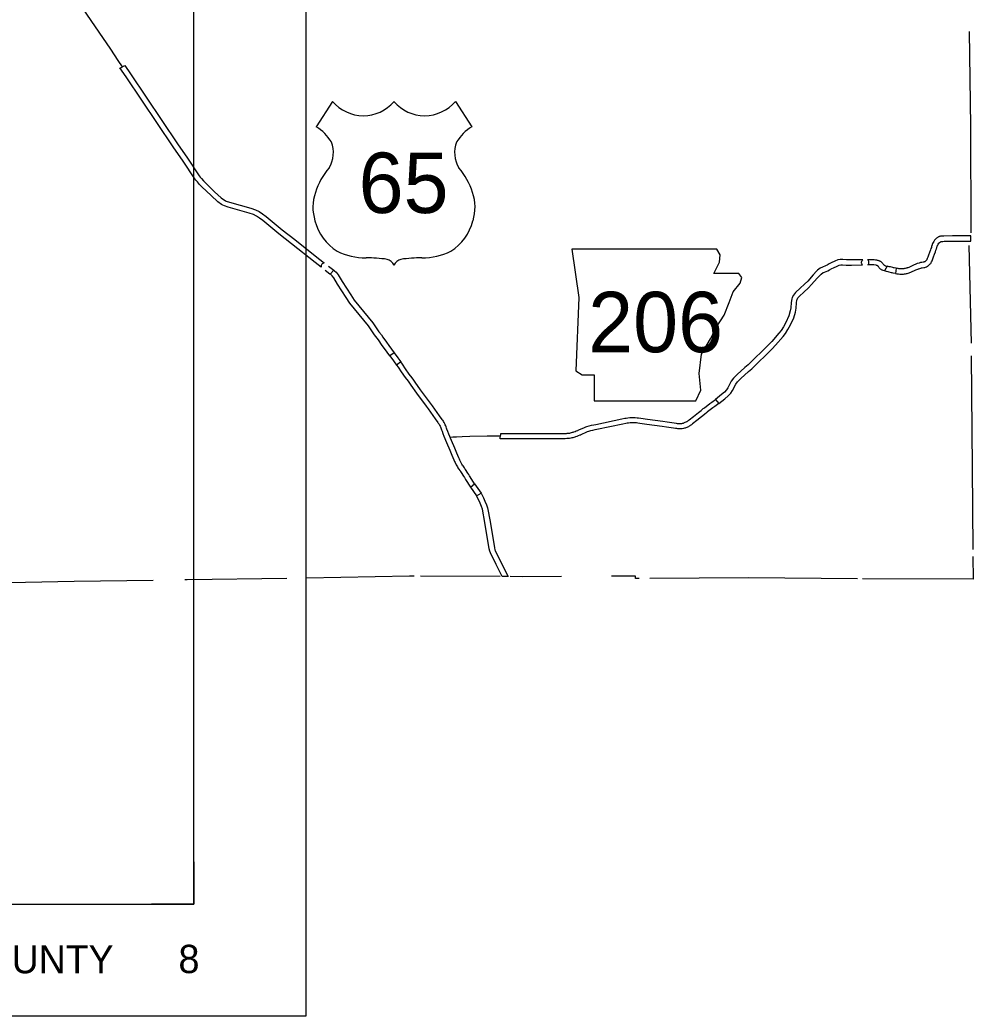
# Model space of a CAD drawing. Extents: x 77230 to 630905, y 790554 to 1662844.
# Drawn here: x 578093 to 623064, y 1483324 to 1530346 of the extents above; entities that cross this region are included whole.
import ezdxf

# ---------------------------------------------------------------- set-up
doc = ezdxf.new("R2010")
doc.units = 0
for name, color, linetype in [('Level 10', 7, 'Continuous'), ('Level 15', 7, 'Continuous'), ('Level 24', 7, 'Continuous'), ('Level 25', 7, 'Continuous'), ('Level 28', 7, 'Continuous'), ('Level 43', 7, 'Continuous')]:
    doc.layers.add(name, color=color, linetype=linetype)

msp = doc.modelspace()

# ---------------------------------------------------------------- linework, layer by layer
at = {"layer": 'Level 10'}
for points in [[(619605, 1518350), (619655, 1518346), (619690, 1518346), (619740, 1518348), (619780, 1518349), (619831, 1518354), (619876, 1518362), (619920, 1518370), (619961, 1518380), (620001, 1518389), (620042, 1518402), (620085, 1518418), (620130, 1518438), (620359, 1518544), (620459, 1518586), (620483, 1518596), (620500, 1518603), (620595, 1518630), (620633, 1518644), (620641, 1518646), (620644, 1518647), (620670, 1518650), (620742, 1518656), (620785, 1518665), (620822, 1518678), (620864, 1518695), (620907, 1518716), (620952, 1518745), (620984, 1518770), (621016, 1518798), (621042, 1518826), (621065, 1518852), (621081, 1518878), (621094, 1518900), (621107, 1518923), (621131, 1518977), (621149, 1519018), (621166, 1519067), (621198, 1519162), (621245, 1519290), (621285, 1519405), (621308, 1519470), (621327, 1519511), (621340, 1519543), (621346, 1519562), (621352, 1519582), (621369, 1519663), (621371, 1519670), (621377, 1519681), (621398, 1519718), (621422, 1519757), (621452, 1519803), (621458, 1519811), (621467, 1519821), (621480, 1519833), (621495, 1519847), (621508, 1519856), (621523, 1519866), (621540, 1519877), (621543, 1519878), (621544, 1519879), (621550, 1519881), (621559, 1519884), (621563, 1519886), (621570, 1519887), (621597, 1519891), (621633, 1519894), (621694, 1519895), (622100, 1519899), (622957, 1519897)], [(622957, 1519897), (622958, 1520147), (622099, 1520149), (621690, 1520145), (621620, 1520144), (621572, 1520139), (621526, 1520134), (621497, 1520127), (621480, 1520122), (621464, 1520116), (621447, 1520110), (621427, 1520100), (621411, 1520091), (621389, 1520077), (621364, 1520061), (621336, 1520040), (621310, 1520017), (621286, 1519993), (621264, 1519969), (621249, 1519948), (621211, 1519891), (621184, 1519847), (621154, 1519796), (621137, 1519759), (621127, 1519727), (621110, 1519645), (621107, 1519637), (621105, 1519629), (621097, 1519611), (621076, 1519563), (621049, 1519488), (621009, 1519374), (620962, 1519245), (620930, 1519149), (620916, 1519109), (620902, 1519078), (620882, 1519033), (620877, 1519023), (620869, 1519011), (620863, 1519002), (620855, 1518993), (620841, 1518977), (620825, 1518963), (620807, 1518949), (620783, 1518933), (620762, 1518923), (620735, 1518912), (620718, 1518906), (620706, 1518904), (620647, 1518899), (620608, 1518895), (620579, 1518889), (620551, 1518880), (620517, 1518867), (620424, 1518841), (620392, 1518830), (620361, 1518816), (620258, 1518772), (620027, 1518666), (619989, 1518649), (619959, 1518638), (619936, 1518630), (619906, 1518623), (619868, 1518615), (619831, 1518608), (619799, 1518602), (619763, 1518599), (619731, 1518597), (619687, 1518596), (619665, 1518596), (619622, 1518600)], [(617860, 1519028), (617323, 1519023), (617091, 1519027), (616914, 1519038), (616797, 1519034), (616682, 1519014), (616546, 1518959), (616372, 1518876), (616272, 1518825), (616180, 1518770), (616107, 1518736), (615958, 1518677), (615857, 1518630), (615730, 1518531), (615675, 1518481), (615525, 1518321), (615261, 1518020), (615117, 1517871), (614906, 1517677), (614687, 1517486), (614586, 1517356), (614533, 1517244)], [(617853, 1518778), (617840, 1518793), (617818, 1518830), (617807, 1518864), (617804, 1518914), (617816, 1518964), (617829, 1518990), (617860, 1519028)], [(618096, 1519030), (618394, 1519032)], [(618106, 1518780), (618126, 1518805), (618141, 1518834), (618153, 1518881), (618147, 1518947), (618120, 1519002), (618096, 1519030)], [(618394, 1519032), (618464, 1519023), (618513, 1519015), (618545, 1519009), (618576, 1519002), (618598, 1518995), (618619, 1518987), (618638, 1518979), (618663, 1518968), (618686, 1518955), (618712, 1518939), (618742, 1518915), (618764, 1518895), (618782, 1518875), (618802, 1518850), (618821, 1518823), (618835, 1518806), (618850, 1518788), (618857, 1518781), (618862, 1518776), (618867, 1518772), (618872, 1518769), (618885, 1518762), (618902, 1518754), (618921, 1518746), (618943, 1518738), (619004, 1518719), (618883, 1518500)], [(614766, 1517151), (614800, 1517224), (614869, 1517314), (615073, 1517490), (615292, 1517692), (615445, 1517850), (615710, 1518153), (615850, 1518302), (615891, 1518339), (615988, 1518416), (616057, 1518447), (616207, 1518506), (616297, 1518549), (616393, 1518606), (616482, 1518651), (616647, 1518730), (616751, 1518773), (616823, 1518785), (616910, 1518788), (617081, 1518777), (617322, 1518773), (617853, 1518778)], [(618389, 1518782), (618106, 1518780)], [(618883, 1518500), (618829, 1518514), (618799, 1518526), (618772, 1518539), (618745, 1518554), (618724, 1518567), (618702, 1518584), (618684, 1518600), (618667, 1518618), (618641, 1518647), (618620, 1518674), (618601, 1518701), (618592, 1518713), (618586, 1518719), (618580, 1518724), (618568, 1518733), (618556, 1518741), (618549, 1518746), (618539, 1518750), (618529, 1518754), (618520, 1518757), (618510, 1518760), (618492, 1518765), (618470, 1518769), (618389, 1518782)], [(619408, 1518373), (619291, 1518399), (619255, 1518407), (619220, 1518415), (619111, 1518441), (619060, 1518451), (618977, 1518468), (618933, 1518479), (618883, 1518500)], [(619437, 1518621), (619347, 1518643), (619309, 1518651), (619277, 1518658), (619163, 1518686), (619108, 1518696), (619004, 1518719)], [(619622, 1518600), (619569, 1518603), (619531, 1518607), (619503, 1518609), (619437, 1518621), (619408, 1518373)], [(619408, 1518373), (619472, 1518361), (619509, 1518358), (619549, 1518354), (619605, 1518350)], [(614533, 1517244), (614513, 1517183), (614485, 1517015), (614466, 1516763), (614440, 1516610), (614368, 1516379), (614229, 1516066), (614117, 1515861), (614006, 1515691), (613907, 1515561), (613563, 1515162), (613414, 1515003), (612457, 1514065), (612297, 1513932), (611934, 1513604), (611766, 1513431), (611655, 1513287), (611491, 1512982), (611428, 1512885), (611335, 1512779), (611194, 1512658), (610908, 1512433), (611063, 1512237)], [(611063, 1512237), (611353, 1512465), (611511, 1512601), (611628, 1512734), (611706, 1512855), (611865, 1513151), (611955, 1513266), (612108, 1513424), (612461, 1513743), (612625, 1513879), (613592, 1514828), (613748, 1514995), (614101, 1515404), (614210, 1515547), (614331, 1515732), (614454, 1515955), (614602, 1516291), (614683, 1516552), (614714, 1516733), (614733, 1516985), (614756, 1517123), (614766, 1517151)], [(604835, 1511156), (604950, 1511185), (605058, 1511210), (605169, 1511234), (605269, 1511253), (606492, 1511510), (606632, 1511543), (606703, 1511555), (606772, 1511566), (606865, 1511577), (606960, 1511581), (607048, 1511581), (607118, 1511577), (607209, 1511568), (607285, 1511558), (607382, 1511546), (607709, 1511498), (608429, 1511399), (608627, 1511370), (608969, 1511323), (609052, 1511310), (609105, 1511303), (609146, 1511300), (609180, 1511298), (609220, 1511297), (609265, 1511297), (609316, 1511300), (609354, 1511305), (609380, 1511310), (609397, 1511316), (609419, 1511325), (609451, 1511338), (609484, 1511354), (609520, 1511370), (609554, 1511388), (609572, 1511398), (609589, 1511409), (609612, 1511423), (609634, 1511439), (609675, 1511471), (609869, 1511625), (610103, 1511816), (610240, 1511913), (610333, 1511998), (610386, 1512041), (610641, 1512234), (610738, 1512307), (610908, 1512433), (611063, 1512237)], [(611063, 1512237), (610887, 1512106), (610791, 1512035), (610540, 1511844), (610495, 1511808), (610397, 1511718), (610255, 1511617), (610026, 1511430), (609829, 1511274), (609784, 1511239), (609750, 1511214), (609720, 1511196), (609702, 1511185), (609677, 1511170), (609630, 1511145), (609588, 1511126), (609553, 1511110), (609514, 1511093), (609483, 1511081), (609445, 1511068), (609395, 1511058), (609338, 1511051), (609273, 1511047), (609215, 1511047), (609168, 1511049), (609129, 1511051), (609080, 1511055), (609017, 1511063), (608933, 1511076), (608592, 1511123), (608394, 1511152), (607673, 1511250), (607348, 1511298), (607253, 1511310), (607180, 1511320), (607098, 1511328), (607040, 1511331), (606966, 1511331), (606885, 1511328), (606805, 1511318), (606745, 1511309), (606683, 1511298), (606546, 1511266), (605317, 1511007), (605219, 1510989), (605113, 1510966), (605009, 1510942), (604914, 1510918)], [(604914, 1510918), (604863, 1510896), (604827, 1510879), (604559, 1510761), (604535, 1510750), (604510, 1510740), (604431, 1510709), (604371, 1510686), (604313, 1510667), (604271, 1510653), (604226, 1510639), (604181, 1510627), (604137, 1510614), (604081, 1510600), (604029, 1510592), (603982, 1510587), (603936, 1510583), (603891, 1510581), (603811, 1510577), (603408, 1510577), (602990, 1510577), (602545, 1510577), (601722, 1510577), (601409, 1510577), (600745, 1510574)], [(600788, 1510824), (601408, 1510827), (601722, 1510827), (602545, 1510827), (602990, 1510827), (603408, 1510827), (603806, 1510827), (603878, 1510830), (603919, 1510833), (603957, 1510836), (603996, 1510840), (604032, 1510846), (604072, 1510855), (604112, 1510867), (604157, 1510880), (604196, 1510891), (604234, 1510904), (604287, 1510921), (604340, 1510942), (604415, 1510971), (604435, 1510980), (604458, 1510990), (604724, 1511107), (604761, 1511124), (604800, 1511141), (604835, 1511156)], [(599318, 1510681), (598964, 1510671), (598691, 1510658), (598519, 1510647), (598395, 1510639)], [(600772, 1510699), (600141, 1510696), (599317, 1510681)]]:
    msp.add_lwpolyline(points, dxfattribs=at)
msp.add_arc((599357, 1510942), 1435, 345.1612, 355.3083, dxfattribs=at)
at = {"layer": 'Level 15'}
for points in [[(580426, 1531556), (580484, 1531517), (580674, 1531354), (580755, 1531280), (580835, 1531194), (580892, 1531123), (582361, 1528958), (582710, 1528428)], [(582710, 1528428), (582923, 1528130)], [(590301, 1520252), (589549, 1520871), (589392, 1520992), (589254, 1521085), (589106, 1521154), (588912, 1521223), (587912, 1521507), (587740, 1521564), (587662, 1521599), (587610, 1521629), (587429, 1521761), (587108, 1522055), (586668, 1522473), (586568, 1522579), (586464, 1522697), (586397, 1522780), (586345, 1522852), (585799, 1523680), (585328, 1524363), (583105, 1527660), (582806, 1528078)], [(583036, 1528187), (583310, 1527802), (585535, 1524503), (586006, 1523819), (586552, 1522993), (586596, 1522931), (586655, 1522858), (586753, 1522747), (586845, 1522650), (587279, 1522237), (587588, 1521955), (587748, 1521838), (587777, 1521821), (587831, 1521797), (587986, 1521746), (588988, 1521461), (589201, 1521386), (589378, 1521303), (589538, 1521195), (589705, 1521067), (590460, 1520445)], [(592299, 1518680), (592023, 1518894), (590902, 1519783), (590301, 1520252)], [(590460, 1520445), (591056, 1519980), (592178, 1519091), (592452, 1518877)], [(592496, 1518530), (592719, 1518363), (592738, 1518347)], [(592646, 1518730), (592906, 1518535)], [(592738, 1518347), (592905, 1518534), (592935, 1518508), (593008, 1518438), (593115, 1518308), (593289, 1518002), (593699, 1517375), (593858, 1517122), (594738, 1516053), (595031, 1515626), (595149, 1515480), (595223, 1515378), (595382, 1515128), (595495, 1514985), (595754, 1514630)], [(595754, 1514630), (595548, 1514489), (595296, 1514833), (595178, 1514983), (595016, 1515238), (594950, 1515328), (594830, 1515476), (594538, 1515903), (593655, 1516975), (593488, 1517240), (593075, 1517872), (592909, 1518166), (592824, 1518268), (592769, 1518322), (592738, 1518347)], [(595754, 1514630), (595927, 1514393), (596064, 1514199)], [(595548, 1514489), (595724, 1514248), (595859, 1514057)], [(597890, 1511657), (597563, 1512129), (597458, 1512262), (597000, 1512881), (596748, 1513240), (596685, 1513339), (596605, 1513448), (596462, 1513622), (596280, 1513873), (596142, 1514089), (596064, 1514199), (595859, 1514057)], [(595859, 1514057), (595935, 1513949), (596074, 1513732), (596264, 1513469), (596408, 1513295), (596478, 1513199), (596540, 1513101), (596797, 1512735), (597260, 1512110), (597362, 1511981), (597684, 1511515)], [(597684, 1511515), (597813, 1511344), (597830, 1511318), (597847, 1511294), (597868, 1511260), (597889, 1511222), (597915, 1511171), (597932, 1511134), (597949, 1511090), (597968, 1511045), (597988, 1510995), (598008, 1510939), (598052, 1510825), (598100, 1510702), (598225, 1510392), (598376, 1510032), (598473, 1509797), (598565, 1509580), (598583, 1509539), (598599, 1509504), (598625, 1509450), (598680, 1509346), (598731, 1509253), (598759, 1509205), (598791, 1509152), (598859, 1509057), (598881, 1509023), (598907, 1508984), (599015, 1508814), (599062, 1508746), (599099, 1508688), (599120, 1508653), (599350, 1508294), (599546, 1508448)], [(599546, 1508448), (599333, 1508784), (599312, 1508820), (599270, 1508885), (599223, 1508952), (599117, 1509119), (599090, 1509160), (599065, 1509199), (598999, 1509290), (598974, 1509332), (598949, 1509376), (598900, 1509465), (598848, 1509562), (598826, 1509610), (598811, 1509642), (598795, 1509679), (598703, 1509893), (598607, 1510128), (598456, 1510488), (598332, 1510794), (598286, 1510915), (598242, 1511027), (598222, 1511083), (598200, 1511139), (598181, 1511186), (598162, 1511232), (598140, 1511279), (598110, 1511340), (598083, 1511387), (598056, 1511430), (598036, 1511460), (598015, 1511490), (597890, 1511657)], [(599350, 1508294), (599629, 1507886)], [(599546, 1508448), (599849, 1508004)], [(599629, 1507886), (599849, 1508004), (599965, 1507788), (600033, 1507637), (600104, 1507458)], [(599869, 1507371), (599803, 1507540), (599741, 1507678), (599629, 1507886)], [(601128, 1504066), (600847, 1504068), (600558, 1504636), (600293, 1505198), (600268, 1505263), (600240, 1505382), (600028, 1506626), (599912, 1507249), (599869, 1507371)], [(600104, 1507458), (600154, 1507313), (600274, 1506670), (600485, 1505432), (600507, 1505337), (600523, 1505296), (600783, 1504746), (601128, 1504066)]]:
    msp.add_lwpolyline(points, dxfattribs=at)
for centre, radius, start, end in [((581559, 1531008), 3184, 293.0661, 297.6373), ((592473, 1518703), 175, 96.6048, 187.7743)]:
    msp.add_arc(centre, radius, start, end, dxfattribs=at)
at = {"layer": 'Level 24'}
msp.add_lwpolyline([(604128, 1519524), (604470, 1517240), (604318, 1513776), (604623, 1513586), (605194, 1513586), (605194, 1512368), (609990, 1512368), (610218, 1512863), (610142, 1513662), (610256, 1514576), (610675, 1515299), (610941, 1515832), (611322, 1516403), (611551, 1517012), (611741, 1517507), (612083, 1517925), (612160, 1518192), (612007, 1518382), (610827, 1518382), (611094, 1518915), (611132, 1519258), (610974, 1519521)], close=True, dxfattribs=at)
msp.add_lwpolyline([(604128, 1519524), (604470, 1517240), (604318, 1513776), (604623, 1513586), (605194, 1513586), (605194, 1512368), (609990, 1512368), (610218, 1512863), (610142, 1513662), (610256, 1514576), (610675, 1515299), (610941, 1515832), (611322, 1516403), (611551, 1517012), (611741, 1517507), (612083, 1517925), (612160, 1518192), (612007, 1518382), (610827, 1518382), (611094, 1518915), (611132, 1519258), (610974, 1519521)], close=True, dxfattribs=at)
at = {"layer": 'Level 25'}
for p, q in [((592846, 1526501), (592067, 1525296)), ((598637, 1526501), (599416, 1525296))]:
    msp.add_line(p, q, dxfattribs=at)
for centre, radius, start, end in [((594297, 1527721), 1896, 220.075, 319.6701), ((597187, 1527721), 1896, 220.3299, 319.925), ((591050, 1523548), 2024, 30.7809, 59.9883), ((600434, 1523548), 2024, 120.0117, 149.2191), ((591495, 1524081), 1387, 328.8105, 21.2108), ((599989, 1524081), 1387, 158.7892, 211.1895), ((595123, 1521238), 3236, 138.9565, 162.6913), ((596361, 1521238), 3236, 17.3087, 41.0435), ((594054, 1521503), 2138, 160.9576, 197.3819), ((597430, 1521503), 2138, 342.6181, 19.0424), ((594402, 1521509), 2474, 195.1074, 237.1312), ((597081, 1521509), 2474, 302.8688, 344.8926), ((594448, 1522288), 3177, 244.0771, 269.5779), ((597035, 1522288), 3177, 270.4221, 295.9229), ((594522, 1513292), 5820, 81.1942, 90.9539), ((595250, 1518510), 558, 28.0342, 72.9864), ((596234, 1518510), 558, 107.0136, 151.9658), ((596962, 1513292), 5820, 89.0461, 98.8058)]:
    msp.add_arc(centre, radius, start, end, dxfattribs=at)
at = {"layer": 'Level 28'}
for p, q in [((591576, 1662844), (591576, 1483324)), ((586296, 1488604), (586296, 1658884)), ((586296, 1499164), (586296, 1499164)), ((586296, 1488604), (586296, 1491097)), ((586296, 1488604), (586296, 1490604)), ((586296, 1490604), (586296, 1488604)), ((311736, 1488604), (586296, 1488604)), ((583974, 1488604), (586296, 1488604)), ((586296, 1488604), (584296, 1488604)), ((586296, 1488604), (584591, 1488604)), ((586296, 1488604), (586296, 1488604)), ((586296, 1488604), (586296, 1488604)), ((586296, 1488604), (586296, 1488604)), ((591576, 1483324), (295896, 1483324))]:
    msp.add_line(p, q, dxfattribs=at)
at = {"layer": 'Level 43'}
for points in [[(622880, 1529794), (622939, 1525327), (622957, 1520289)], [(622868, 1519696), (622970, 1515095)], [(622982, 1514495), (623019, 1509219)], [(623019, 1509219), (623053, 1505348)], [(623055, 1505010), (623064, 1503954), (617844, 1503962)], [(584379, 1503890), (580655, 1503830), (580648, 1503830), (576808, 1503754)], [(590683, 1503985), (585988, 1503916), (585973, 1503915), (585880, 1503914)], [(596696, 1504092), (596481, 1504093), (591621, 1504001)], [(600750, 1504068), (596999, 1504090)], [(603653, 1504071), (601787, 1504062), (601216, 1504066)], [(607315, 1503981), (607138, 1503980), (607139, 1504087), (606004, 1504082)], [(617619, 1503963), (612467, 1504017), (607806, 1503985)]]:
    msp.add_lwpolyline(points, dxfattribs=at)

# ---------------------------------------------------------------- texts
at = {"layer": 'Level 24'}
msp.add_text('206', height=2851.2, dxfattribs=at).set_placement((604904, 1514660))
msp.add_text('206', height=2851.2, dxfattribs=at).set_placement((604904, 1514660))
at = {"layer": 'Level 25'}
msp.add_text('65', height=2851.2, dxfattribs=at).set_placement((594074, 1521232))
at = {"layer": 'Level 28'}
for s, height, p in [('COUNTY', 1320, (575056, 1485343)), ('8', 1336, (585572, 1485352))]:
    msp.add_text(s, height=height, dxfattribs=at).set_placement(p)

doc.saveas('drawing.dxf')
